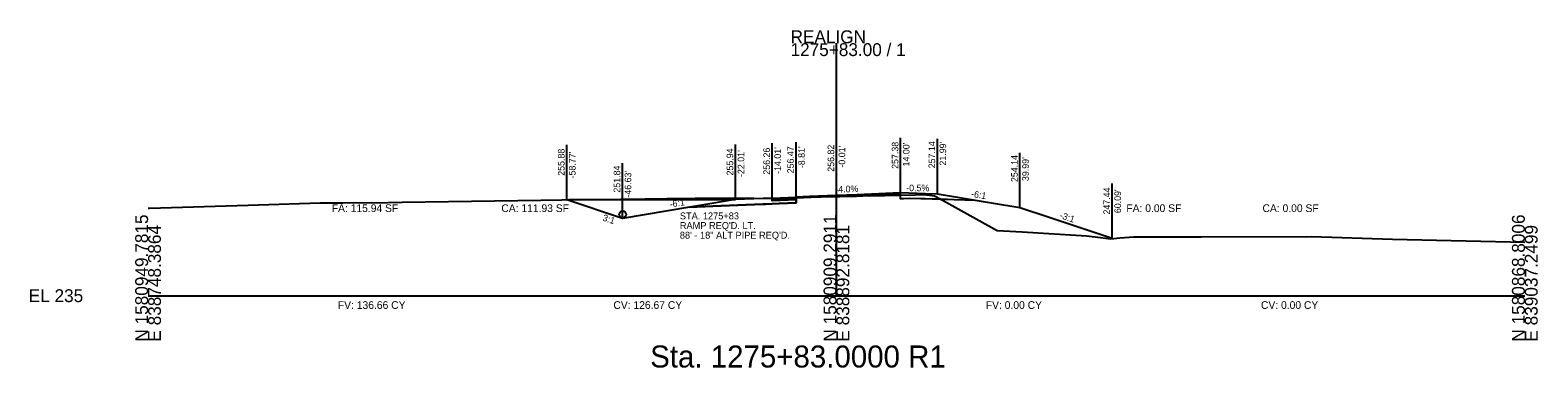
# Model space of a CAD drawing. Extents: x -26 to 6303, y -16 to 9563.
# Drawn here: x 4974.3 to 5302.8, y 9484.3 to 9557.8 of the extents above; entities that cross this region are included whole.
import ezdxf

# ---------------------------------------------------------------- set-up
doc = ezdxf.new("R2010")
doc.units = 0
for name, color, linetype in [('ASPHALT_19MM1', 7, 'Continuous'), ('ASPHALT_9_5MM1', 7, 'Continuous'), ('Default', 7, 'Continuous'), ('Draft_XS_Grid', 7, 'Continuous'), ('Draft_XS_Text', 7, 'Continuous'), ('DTM_TEMP_DROP', 7, 'Continuous'), ('DTM_X_GROUND', 7, 'Continuous'), ('X_TRANS_EOP', 7, 'Continuous'), ('XS_CELL', 7, 'Continuous'), ('XS_M_SHAPES_EARTHWORK', 7, 'Continuous'), ('XS_P_ASPHALT', 7, 'Continuous'), ('XS_P_DRAINAGE', 7, 'Continuous'), ('XS_P_DRIVEWAY', 7, 'Continuous'), ('XS_P_GROUND', 7, 'Continuous'), ('XS_P_SHOULDER', 7, 'Continuous'), ('XS_P_SUBGRADE_GRANULAR', 7, 'Continuous'), ('XS_P_SUBGRADE_LEVELING', 7, 'Continuous'), ('XS_P_SUBGRADE_MILLING', 7, 'Continuous'), ('XS_P_TX_CLEARZONE', 7, 'Continuous'), ('XS_P_TX_FS_BS', 7, 'Continuous'), ('XS_SHEET_EW_TX_AREA', 7, 'Continuous'), ('XS_SHEET_EW_TX_VOLUME', 7, 'Continuous')]:
    doc.layers.add(name, color=color, linetype=linetype)

msp = doc.modelspace()

# ---------------------------------------------------------------- linework, layer by layer
at = {"layer": 'ASPHALT_19MM1'}
msp.add_lwpolyline([(5141.19, 9521.13), (5141.19, 9520.86), (5135.99, 9520.66), (5135.99, 9520.93), (5141.19, 9521.13)], dxfattribs=at)
at = {"layer": 'ASPHALT_9_5MM1'}
msp.add_lwpolyline([(5141.19, 9521.47), (5141.19, 9521.34), (5135.99, 9521.13), (5135.99, 9521.26), (5141.19, 9521.47)], dxfattribs=at)
at = {"layer": 'Default'}
msp.add_lwpolyline([(5141.19, 9521.34), (5141.19, 9521.13), (5135.99, 9520.93), (5135.99, 9521.13), (5141.19, 9521.34)], dxfattribs=at)
at = {"layer": 'DTM_X_GROUND'}
msp.add_lwpolyline([(5000, 9519.07), (5000.33, 9519.08), (5021.79, 9519.75), (5037.52, 9520.26), (5042.44, 9520.24), (5052.25, 9520.33), (5055.36, 9520.36), (5085.56, 9520.8), (5090.14, 9520.89), (5094.23, 9520.92), (5098.87, 9520.95), (5102.97, 9521.01), (5108.24, 9521.08), (5113.01, 9521.14), (5119.19, 9521.23), (5122.76, 9521.27), (5132, 9521.21), (5136.42, 9521.16), (5140.37, 9521.39), (5141.19, 9521.44), (5143.21, 9521.48), (5155.06, 9521.73), (5167.23, 9521.99), (5169.08, 9522.03), (5170.85, 9521.82), (5171.38, 9521.76), (5173.88, 9520.37), (5185.04, 9514.2), (5190.46, 9513.88), (5204.48, 9513.03), (5206.37, 9512.81), (5209.79, 9512.41), (5211.78, 9512.58), (5214.8, 9512.83), (5220.73, 9512.82), (5229.48, 9512.79), (5253.5, 9512.88), (5271.16, 9512.32), (5300, 9511.69)], dxfattribs=at)
at = {"layer": 'XS_CELL'}
for p, q in [((5150, 9500), (5150, 9555)), ((5000, 9500), (5150, 9500)), ((5150, 9500), (5300, 9500))]:
    msp.add_line(p, q, dxfattribs=at)
at = {"layer": 'XS_M_SHAPES_EARTHWORK'}
for points in [[(5091.23, 9520.88), (5091.23, 9520.9), (5094.23, 9520.92), (5098.87, 9520.95), (5102.97, 9521.01), (5108.24, 9521.08), (5113.01, 9521.14), (5119.19, 9521.23), (5122.76, 9521.27), (5132, 9521.21), (5136.42, 9521.16), (5140.37, 9521.39), (5141.19, 9521.44), (5143.21, 9521.48), (5152.96, 9521.68), (5150.77, 9521.64), (5149.99, 9521.62), (5147.93, 9521.58), (5146.69, 9521.55), (5146.08, 9521.54), (5142.89, 9521.41), (5141.19, 9521.34), (5141.19, 9521.13), (5141.19, 9520.86), (5141.19, 9520.2), (5137.52, 9520.05), (5135.99, 9519.99), (5134.63, 9519.93), (5133.99, 9519.91), (5123.07, 9519.47), (5117.96, 9519.27), (5103.37, 9516.84)], [(5152.96, 9521.68), (5155.06, 9521.73), (5154.37, 9521.71)], [(5157.16, 9521.77), (5163.99, 9521.92), (5163.86, 9521.92), (5161.57, 9521.87)], [(5163.99, 9521.92), (5167.23, 9521.99), (5169.08, 9522.03), (5170.85, 9521.82), (5171.38, 9521.76), (5172.78, 9520.99), (5165.99, 9521.19), (5164.63, 9521.13), (5163.99, 9521.11)], [(5172.78, 9520.99), (5173.88, 9520.37), (5185.04, 9514.2), (5190.46, 9513.88), (5204.48, 9513.03), (5206.37, 9512.81), (5209.79, 9512.41), (5210.09, 9512.44), (5196.39, 9517.01), (5189.99, 9519.14), (5184.21, 9520.1), (5180.26, 9520.76), (5175.68, 9520.9)]]:
    msp.add_lwpolyline(points, close=True, dxfattribs=at)
at = {"layer": 'XS_P_ASPHALT'}
msp.add_lwpolyline([(5141.19, 9521.38), (5141.19, 9521.34), (5144.13, 9521.46), (5149.99, 9521.69), (5154.46, 9521.87), (5163.99, 9522.25), (5163.99, 9522.29), (5163.99, 9522.38), (5154.46, 9522), (5149.99, 9521.82), (5144.13, 9521.59), (5141.19, 9521.47), (5141.19, 9521.38)], dxfattribs=at)
at = {"layer": 'XS_P_DRAINAGE'}
msp.add_circle((5103.41, 9517.69), 0.75, dxfattribs=at)
at = {"layer": 'XS_P_DRIVEWAY'}
msp.add_line((5127.99, 9520.86), (5091.71, 9520.89), dxfattribs=at)
at = {"layer": 'XS_P_GROUND'}
for points in [[(5127.99, 9520.94), (5103.37, 9516.84), (5091.23, 9520.88)], [(5210.09, 9512.44), (5196.39, 9517.01), (5189.99, 9519.14), (5184.21, 9520.1), (5171.99, 9522.14)]]:
    msp.add_lwpolyline(points, dxfattribs=at)
at = {"layer": 'XS_P_SHOULDER'}
for points in [[(5135.99, 9521.26), (5127.99, 9520.94)], [(5171.99, 9522.14), (5169.42, 9522.22), (5163.99, 9522.38)]]:
    msp.add_lwpolyline(points, dxfattribs=at)
at = {"layer": 'XS_P_SUBGRADE_GRANULAR'}
for points in [[(5141.19, 9520.2), (5141.19, 9521.47)], [(5163.99, 9521.11), (5163.99, 9522.38)], [(5180.26, 9520.76), (5175.68, 9520.9), (5165.99, 9521.19), (5164.63, 9521.13), (5163.99, 9521.11)], [(5117.96, 9519.27), (5123.07, 9519.47), (5133.99, 9519.91), (5134.63, 9519.93), (5135.99, 9519.99)], [(5135.99, 9519.99), (5137.52, 9520.05), (5141.19, 9520.2)]]:
    msp.add_lwpolyline(points, dxfattribs=at)
at = {"layer": 'XS_P_SUBGRADE_LEVELING'}
msp.add_lwpolyline([(5141.19, 9521.34), (5142.89, 9521.41), (5146.08, 9521.54), (5146.69, 9521.55), (5147.93, 9521.58), (5149.99, 9521.62), (5150.77, 9521.64), (5154.37, 9521.71), (5155.06, 9521.73), (5155.77, 9521.74), (5161.57, 9521.87), (5163.86, 9521.92), (5163.99, 9521.92), (5163.99, 9522.03), (5163.99, 9522.25), (5163.86, 9522.25), (5161.57, 9522.16), (5155.77, 9521.93), (5155.06, 9521.9), (5154.37, 9521.87), (5150.77, 9521.73), (5149.99, 9521.69), (5147.93, 9521.61), (5144.98, 9521.49), (5141.19, 9521.34), (5141.19, 9521.34)], dxfattribs=at)
at = {"layer": 'XS_P_SUBGRADE_MILLING'}
msp.add_lwpolyline([(5163.99, 9521.92), (5163.99, 9521.92), (5163.86, 9521.92), (5161.57, 9521.87), (5155.77, 9521.74), (5155.06, 9521.73), (5154.37, 9521.71), (5150.77, 9521.64), (5149.99, 9521.62), (5147.93, 9521.58), (5144.98, 9521.52), (5141.19, 9521.44), (5141.19, 9521.38), (5141.19, 9521.34), (5142.89, 9521.41), (5146.08, 9521.54), (5146.69, 9521.55), (5147.93, 9521.58), (5149.99, 9521.62), (5150.77, 9521.64), (5154.37, 9521.71), (5155.06, 9521.73), (5155.77, 9521.74), (5161.57, 9521.87), (5163.86, 9521.92), (5163.99, 9521.92)], dxfattribs=at)
at = {"layer": 'XS_P_TX_CLEARZONE'}
for p, q in [((5163.99, 9522.38), (5163.99, 9534.38)), ((5171.99, 9522.14), (5171.99, 9534.14)), ((5091.23, 9520.88), (5091.23, 9532.88)), ((5127.99, 9520.94), (5127.99, 9532.94)), ((5135.99, 9521.26), (5135.99, 9533.26)), ((5141.19, 9521.47), (5141.19, 9533.47)), ((5149.99, 9521.82), (5149.99, 9533.82)), ((5189.99, 9519.14), (5189.99, 9531.14)), ((5103.37, 9516.84), (5103.37, 9528.84)), ((5210.09, 9512.44), (5210.09, 9524.44))]:
    msp.add_line(p, q, dxfattribs=at)

# ---------------------------------------------------------------- texts
at = {"layer": 'Draft_XS_Grid'}
msp.add_text('-', height=0.0001, dxfattribs=at).set_placement((5000, 9500))
at = {"layer": 'Draft_XS_Text'}
msp.add_text('Sta. 1275+83.0000 R1', height=4.8, dxfattribs=at).set_placement((5109.41, 9484.35))
at = {"layer": 'DTM_TEMP_DROP'}
for p in [(5135.91, 9521.14), (5141.11, 9521.35), (5149.91, 9521.7), (5163.91, 9522.26)]:
    msp.add_text('X', height=0.24, dxfattribs=at).set_placement(p)
at = {"layer": 'X_TRANS_EOP'}
for p in [(5091.15, 9520.76), (5210.01, 9512.32)]:
    msp.add_text('X', height=0.24, dxfattribs=at).set_placement(p)
at = {"layer": 'XS_CELL'}
for s, p in [('REALIGN', (5140, 9555)), ('1275+83.00 / 1', (5140, 9552.2)), ('EL 235', (4974, 9498.6))]:
    msp.add_text(s, height=2.8, dxfattribs=at).set_placement(p)
for s, p in [('N 1580949.7815', (5000, 9490)), ('E 838748.3864', (5002.8, 9490)), ('N 1580909.2911', (5150, 9490)), ('E 838892.8181', (5152.8, 9490)), ('N 1580868.8006', (5300, 9490)), ('E 839037.2499', (5302.8, 9490))]:
    msp.add_text(s, height=2.8, rotation=90, dxfattribs=at).set_placement(p)
at = {"layer": 'XS_P_ASPHALT'}
msp.add_text('X', height=0.24, dxfattribs=at).set_placement((5189.91, 9519.02))
at = {"layer": 'XS_P_DRIVEWAY'}
for s, p in [('STA. 1275+83', (5115.88, 9516.63)), ("RAMP REQ'D. LT.", (5115.88, 9514.53)), ('88\' - 18" ALT PIPE REQ\'D.', (5115.88, 9512.43))]:
    msp.add_text(s, height=1.5, dxfattribs=at).set_placement(p)
at = {"layer": 'XS_P_SHOULDER'}
for p in [(5127.91, 9520.82), (5171.91, 9522.02)]:
    msp.add_text('X', height=0.24, dxfattribs=at).set_placement(p)
at = {"layer": 'XS_P_SUBGRADE_GRANULAR'}
for p in [(5103.3, 9516.72), (5210.01, 9512.32)]:
    msp.add_text('X', height=0.24, dxfattribs=at).set_placement(p)
at = {"layer": 'XS_P_TX_CLEARZONE'}
for s, p in [('255.88', (5090.75, 9526.13)), ("-58.77'", (5093.15, 9525.54)), ('255.94', (5127.51, 9526.19)), ("-22.01'", (5129.91, 9525.85)), ('256.26', (5135.51, 9526.36)), ("-14.01'", (5137.91, 9526.53)), ('256.47', (5140.71, 9526.65)), ("-8.81'", (5143.11, 9527.78)), ('256.82', (5149.51, 9527)), ("-0.01'", (5151.91, 9527.9)), ('257.38', (5163.51, 9527.63)), ("14.00'", (5165.92, 9528.15)), ('257.14', (5171.51, 9527.75)), ("21.99'", (5173.91, 9528.34)), ('251.84', (5102.89, 9522.45)), ('254.14', (5189.51, 9524.75)), ("39.99'", (5191.91, 9524.97)), ("-46.63'", (5105.29, 9521.36)), ('247.44', (5209.61, 9517.68)), ("60.09'", (5212.01, 9517.98))]:
    msp.add_text(s, height=1.44, rotation=90, dxfattribs=at).set_placement(p)
at = {"layer": 'XS_P_TX_FS_BS'}
for s, rotation, p in [('-0.5%', 359.7218, (5165.2, 9522.77)), ('-6:1', 9.4642, (5113.76, 9519.18)), ('-4.0%', 2.2906, (5149.77, 9522.41)), ('-6:1', 350.5376, (5179.26, 9521.54)), ('3:1', 341.5667, (5098.92, 9516.4)), ('-3:1', 341.565, (5198.51, 9516.93))]:
    msp.add_text(s, height=1.44, rotation=rotation, dxfattribs=at).set_placement(p)
at = {"layer": 'XS_SHEET_EW_TX_AREA'}
for s, p in [('FA: 115.94 SF', (5040.03, 9518.22)), ('CA: 111.93 SF', (5076.98, 9518.22)), ('FA: 0.00 SF', (5213.17, 9518.22)), ('CA: 0.00 SF', (5242.84, 9518.22))]:
    msp.add_text(s, height=1.68, dxfattribs=at).set_placement(p)
at = {"layer": 'XS_SHEET_EW_TX_VOLUME'}
for s, p in [('FV: 136.66 CY', (5041.36, 9497.12)), ('CV: 126.67 CY', (5101.4, 9497.12)), ('FV: 0.00 CY', (5182.55, 9497.12)), ('CV: 0.00 CY', (5242.51, 9497.12))]:
    msp.add_text(s, height=1.68, dxfattribs=at).set_placement(p)

doc.saveas('drawing.dxf')
